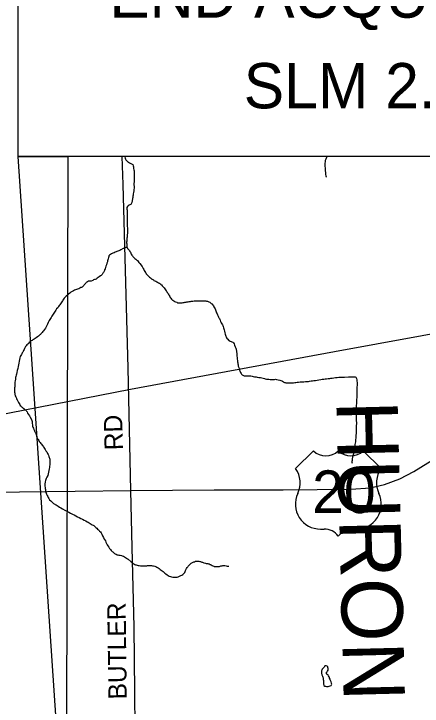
# Model space of a CAD drawing. Extents: x 0 to 34, y 0 to 22.
# Drawn here: x 6.547 to 7.808, y 17.578 to 19.717 of the extents above; entities that cross this region are included whole.
import ezdxf

# ---------------------------------------------------------------- set-up
doc = ezdxf.new("R2010")
doc.units = 0
for name, color, linetype in [('Default', 7, 'Continuous'), ('GM_X_Corporation', 7, 'Continuous'), ('GM_X_County_Road', 7, 'Continuous'), ('GM_X_County_Road_Text', 7, 'Continuous'), ('GM_X_County_Text', 7, 'Continuous'), ('GM_X_Minor_Lake', 7, 'Continuous'), ('GM_X_Minor_River', 7, 'Continuous'), ('GM_X_Rail_Line', 7, 'Continuous'), ('GM_X_US_Location', 7, 'Continuous'), ('GM_X_US_Route', 7, 'Continuous'), ('GM_X_US_Shield', 7, 'Continuous'), ('SH_Text', 7, 'Continuous')]:
    doc.layers.add(name, color=color, linetype=linetype)

msp = doc.modelspace()

# ---------------------------------------------------------------- linework, layer by layer
at = {"layer": 'Default'}
msp.add_lwpolyline([(6.7134, 19.2769), (6.7077, 17.0769), (6.5603, 19.2769)], close=True, dxfattribs=at)
at = {"layer": 'GM_X_Corporation'}
msp.add_lwpolyline([(8.0153, 15.2273), (7.992, 16.4534), (7.9799, 16.8298), (7.9733, 17.0489), (7.973, 17.0583), (7.9659, 17.2939), (7.9575, 17.6697), (7.951, 17.9078), (7.9387, 18.4008), (7.9196, 19.2769), (6.5603, 19.2769), (6.5603, 19.994)], dxfattribs=at)
msp.add_lwpolyline([(8.0153, 15.2273), (7.992, 16.4534), (7.9799, 16.8298), (7.9733, 17.0489), (7.973, 17.0583), (7.9659, 17.2939), (7.9575, 17.6697), (7.951, 17.9078), (7.9387, 18.4008), (7.9196, 19.2769), (6.5603, 19.2769), (6.5603, 19.994)], dxfattribs=at)
at = {"layer": 'GM_X_County_Road'}
for points in [[(6.9082, 18.2451), (6.8994, 18.6225), (6.8843, 19.1906), (6.8812, 19.2769)], [(6.9289, 17.0721), (6.923, 17.2763), (6.9202, 17.6229), (6.9177, 17.8238), (6.9125, 18.0684), (6.9082, 18.2451)]]:
    msp.add_lwpolyline(points, dxfattribs=at)
at = {"layer": 'GM_X_Minor_Lake'}
for points in [[(7.5068, 17.7034), (7.5068, 17.7034), (7.5054, 17.6994), (7.5038, 17.6974), (7.5018, 17.6958), (7.4991, 17.6928), (7.4976, 17.6897), (7.4968, 17.6871), (7.4964, 17.684), (7.4964, 17.6814), (7.4967, 17.6801)], [(7.5068, 17.7034), (7.5068, 17.7034), (7.5054, 17.6994), (7.5038, 17.6974), (7.5018, 17.6958), (7.4991, 17.6928), (7.4976, 17.6897), (7.4968, 17.6871), (7.4964, 17.684), (7.4964, 17.6814), (7.4967, 17.6801)], [(7.4967, 17.6801), (7.4979, 17.6753), (7.4987, 17.6734), (7.4994, 17.6711), (7.5009, 17.668), (7.5017, 17.6658), (7.502, 17.6627), (7.502, 17.6604), (7.5024, 17.6581), (7.5024, 17.6555), (7.5024, 17.6528), (7.5027, 17.6498), (7.5027, 17.6467), (7.5035, 17.6444), (7.5035, 17.6425), (7.5065, 17.6406), (7.5088, 17.6398), (7.5122, 17.6391), (7.5149, 17.639), (7.5175, 17.6394), (7.5206, 17.6401), (7.5233, 17.6409), (7.5267, 17.642), (7.5282, 17.6462), (7.5279, 17.6481), (7.5279, 17.65), (7.5268, 17.6538), (7.526, 17.6557), (7.5249, 17.658), (7.5237, 17.6599), (7.523, 17.6618), (7.5219, 17.6645), (7.5211, 17.6668), (7.52, 17.6694), (7.5188, 17.6717), (7.5173, 17.674), (7.5147, 17.6767), (7.5124, 17.6786), (7.5117, 17.6809), (7.5124, 17.6832), (7.5143, 17.6847), (7.5155, 17.687), (7.517, 17.6896), (7.5174, 17.6953), (7.5167, 17.698), (7.5159, 17.7003), (7.5137, 17.7022), (7.5114, 17.703), (7.5083, 17.7034), (7.5068, 17.7034)], [(7.4967, 17.6801), (7.4979, 17.6753), (7.4987, 17.6734), (7.4994, 17.6711), (7.5009, 17.668), (7.5017, 17.6658), (7.502, 17.6627), (7.502, 17.6604), (7.5024, 17.6581), (7.5024, 17.6555), (7.5024, 17.6528), (7.5027, 17.6498), (7.5027, 17.6467), (7.5035, 17.6444), (7.5035, 17.6425), (7.5065, 17.6406), (7.5088, 17.6398), (7.5122, 17.6391), (7.5149, 17.639), (7.5175, 17.6394), (7.5206, 17.6401), (7.5233, 17.6409), (7.5267, 17.642), (7.5282, 17.6462), (7.5279, 17.6481), (7.5279, 17.65), (7.5268, 17.6538), (7.526, 17.6557), (7.5249, 17.658), (7.5237, 17.6599), (7.523, 17.6618), (7.5219, 17.6645), (7.5211, 17.6668), (7.52, 17.6694), (7.5188, 17.6717), (7.5173, 17.674), (7.5147, 17.6767), (7.5124, 17.6786), (7.5117, 17.6809), (7.5124, 17.6832), (7.5143, 17.6847), (7.5155, 17.687), (7.517, 17.6896), (7.5174, 17.6953), (7.5167, 17.698), (7.5159, 17.7003), (7.5137, 17.7022), (7.5114, 17.703), (7.5083, 17.7034), (7.5068, 17.7034)]]:
    msp.add_lwpolyline(points, dxfattribs=at)
at = {"layer": 'GM_X_Minor_River'}
for points in [[(6.8891, 19.2769), (6.8894, 19.2751), (6.8902, 19.2717), (6.8917, 19.2686), (6.8928, 19.2667), (6.8947, 19.264), (6.8966, 19.2621), (6.8989, 19.2598), (6.9008, 19.2591), (6.9038, 19.2572), (6.9057, 19.256), (6.9076, 19.2552), (6.9095, 19.2541), (6.9118, 19.2533), (6.9141, 19.2514), (6.9156, 19.2476), (6.9159, 19.2442), (6.9163, 19.2396), (6.9174, 19.2351), (6.9178, 19.2324)], [(7.5136, 19.2769), (7.5119, 19.2736), (7.51, 19.2687), (7.5085, 19.2645), (7.5077, 19.2599), (7.5073, 19.2565), (7.5073, 19.2508), (7.5072, 19.2459), (7.5076, 19.2417), (7.508, 19.236), (7.5083, 19.2318), (7.5087, 19.2292), (7.5087, 19.2265), (7.509, 19.2227), (7.5098, 19.2151), (7.5124, 19.2136)], [(6.9178, 19.2324), (6.9181, 19.2278), (6.9185, 19.2221), (6.9185, 19.2168), (6.9184, 19.2126), (6.9184, 19.2096), (6.9184, 19.2062), (6.918, 19.2027), (6.918, 19.1993), (6.918, 19.1967), (6.9176, 19.194), (6.9179, 19.1788), (6.9175, 19.1746), (6.9171, 19.1704), (6.9163, 19.1659), (6.9155, 19.1617), (6.9147, 19.1575), (6.914, 19.1545), (6.9136, 19.1499), (6.9132, 19.1473), (6.9124, 19.1401), (6.9108, 19.1344), (6.9097, 19.1325), (6.9074, 19.1287), (6.9051, 19.1272), (6.9032, 19.126), (6.9001, 19.1238), (6.8978, 19.1219), (6.8959, 19.1192), (6.8959, 19.1139), (6.8963, 19.1109), (6.8962, 19.109), (6.8962, 19.1052), (6.8962, 19.1006), (6.8962, 19.0953), (6.8961, 19.0888), (6.8965, 19.0816), (6.8965, 19.0774), (6.8965, 19.0736), (6.8964, 19.071), (6.8964, 19.0656), (6.8971, 19.0516), (6.8975, 19.0478), (6.8975, 19.0447), (6.8971, 19.0425), (6.8971, 19.0394), (6.8966, 19.0345), (6.8966, 19.0307), (6.8962, 19.0273), (6.8958, 19.0246), (6.8958, 19.0223), (6.8954, 19.0189), (6.8954, 19.0147), (6.895, 19.0124), (6.895, 19.0102), (6.8954, 19.0067), (6.8954, 19.0041), (6.8953, 19.0007), (6.8953, 18.998), (6.8961, 18.9957), (6.898, 18.9919), (6.9006, 18.9888), (6.9033, 18.9858), (6.9052, 18.9831), (6.9067, 18.9808), (6.9093, 18.9744), (6.9112, 18.9713), (6.9131, 18.9694), (6.9142, 18.9675), (6.9172, 18.9648), (6.9188, 18.9629), (6.9207, 18.9614), (6.9233, 18.9595), (6.9263, 18.9568), (6.9286, 18.9549), (6.9309, 18.9526), (6.9331, 18.9495), (6.9354, 18.9461), (6.9426, 18.9366), (6.9445, 18.9331), (6.946, 18.9305), (6.9479, 18.9274), (6.9494, 18.9244), (6.9513, 18.9213), (6.9528, 18.9187), (6.9539, 18.9168), (6.9554, 18.9145), (6.9569, 18.9122), (6.9592, 18.9099), (6.9619, 18.9076), (6.9653, 18.9042), (6.9687, 18.9015), (6.9713, 18.8996), (6.9732, 18.898), (6.9755, 18.8965), (6.9774, 18.8954), (6.9793, 18.8938), (6.9816, 18.8923), (6.9846, 18.8911), (6.9877, 18.8896), (6.9907, 18.8881)], [(6.896, 18.9959), (6.8946, 18.9957), (6.8927, 18.9953), (6.89, 18.9942), (6.8866, 18.9927), (6.8846, 18.992), (6.8766, 18.9878), (6.8736, 18.9863), (6.8675, 18.9837), (6.8648, 18.9829), (6.8621, 18.9818), (6.8591, 18.9807), (6.8564, 18.9792), (6.8526, 18.9784), (6.8499, 18.9773), (6.8477, 18.9758), (6.8446, 18.9743), (6.8419, 18.9713), (6.84, 18.9698), (6.8396, 18.9679), (6.8389, 18.9644), (6.8377, 18.9603), (6.8369, 18.9569), (6.8361, 18.9542), (6.8354, 18.9512), (6.8342, 18.947), (6.8327, 18.9424), (6.8311, 18.9379), (6.8296, 18.9333), (6.8284, 18.9295), (6.8269, 18.9269), (6.8265, 18.9246), (6.8257, 18.9227), (6.8246, 18.9204), (6.823, 18.9182), (6.8215, 18.9159), (6.8192, 18.9121), (6.8165, 18.9091), (6.8142, 18.9076), (6.8104, 18.9049), (6.8074, 18.9026), (6.8039, 18.9004), (6.8009, 18.8981), (6.7978, 18.897), (6.7959, 18.8966), (6.7929, 18.8951), (6.7906, 18.8936), (6.7856, 18.891), (6.7818, 18.891), (6.7795, 18.8914), (6.7776, 18.891), (6.7738, 18.8899), (6.7704, 18.8869), (6.7688, 18.885), (6.7662, 18.8819), (6.7642, 18.8797), (6.7627, 18.8778), (6.7597, 18.8747), (6.7577, 18.8732), (6.7558, 18.8721), (6.7536, 18.8714), (6.7505, 18.8702), (6.7471, 18.8683), (6.7429, 18.8672), (6.7402, 18.8657), (6.7372, 18.865), (6.7341, 18.8635), (6.7307, 18.8616), (6.7269, 18.8597), (6.723, 18.8574), (6.7196, 18.8548), (6.7158, 18.8518), (6.712, 18.8484), (6.7085, 18.8453), (6.7047, 18.8416), (6.7024, 18.8389), (6.7001, 18.8363), (6.6982, 18.8332), (6.6967, 18.8306), (6.6947, 18.8276), (6.6924, 18.8241), (6.6905, 18.8215), (6.6886, 18.8188), (6.6867, 18.8162), (6.6848, 18.8132), (6.6821, 18.809), (6.6787, 18.8056), (6.6764, 18.8018), (6.6679, 18.7897), (6.666, 18.7866), (6.6637, 18.7829), (6.6614, 18.7794), (6.6595, 18.776), (6.658, 18.773), (6.656, 18.7696), (6.653, 18.7635), (6.6507, 18.759), (6.6484, 18.7548), (6.6464, 18.7503), (6.6441, 18.7461), (6.6411, 18.7419)], [(6.9907, 18.8881), (6.9937, 18.8865), (6.9964, 18.885), (6.999, 18.8831), (7.0009, 18.8816), (7.0024, 18.8797), (7.0047, 18.8774), (7.0066, 18.8755), (7.0081, 18.8736), (7.0104, 18.8709), (7.0127, 18.8678), (7.0149, 18.8644), (7.0172, 18.8617), (7.0187, 18.8594), (7.0202, 18.8568), (7.0217, 18.8545), (7.0232, 18.8526), (7.0251, 18.8495), (7.0266, 18.8469), (7.0282, 18.8438), (7.0297, 18.8411), (7.0312, 18.8389), (7.0331, 18.8362), (7.0353, 18.8339), (7.0376, 18.8324), (7.0403, 18.8304), (7.0429, 18.8289), (7.0456, 18.8278), (7.0501, 18.8262), (7.0524, 18.8247), (7.0547, 18.8243), (7.0574, 18.8243), (7.0604, 18.8243), (7.0634, 18.8246), (7.0665, 18.825), (7.0692, 18.8254), (7.0722, 18.8257), (7.0745, 18.8261), (7.0768, 18.8265), (7.0787, 18.8268), (7.081, 18.8272), (7.0848, 18.828), (7.0878, 18.8283), (7.0905, 18.8291), (7.0924, 18.8291), (7.0947, 18.8294), (7.097, 18.8298), (7.0996, 18.8298), (7.103, 18.8305), (7.1061, 18.8305), (7.1095, 18.8309), (7.1137, 18.8309), (7.1194, 18.8308), (7.1236, 18.8304), (7.1274, 18.8304), (7.1304, 18.8304), (7.1331, 18.8304), (7.1354, 18.8304), (7.1377, 18.8304), (7.1396, 18.8303), (7.1415, 18.83), (7.1449, 18.8296), (7.1491, 18.8276), (7.1517, 18.8261), (7.154, 18.8242), (7.1563, 18.8227), (7.1582, 18.8211), (7.1631, 18.815), (7.1646, 18.8124), (7.1661, 18.8093), (7.168, 18.8055), (7.1703, 18.8002), (7.1718, 18.7967), (7.1729, 18.7941), (7.1744, 18.7907), (7.1759, 18.7872), (7.1774, 18.7834), (7.1789, 18.7804), (7.18, 18.7785), (7.1815, 18.7758), (7.1827, 18.7731), (7.1834, 18.7705), (7.1846, 18.7667), (7.1857, 18.7644), (7.1868, 18.7625), (7.1891, 18.7594), (7.191, 18.7567), (7.1917, 18.7545), (7.1928, 18.7514), (7.1944, 18.7476), (7.1958, 18.7415), (7.1973, 18.7366), (7.1985, 18.732), (7.1996, 18.7278), (7.2003, 18.7248), (7.2015, 18.7214), (7.2022, 18.7191), (7.2037, 18.716), (7.2056, 18.7133), (7.2075, 18.7118), (7.209, 18.7095)], [(6.6411, 18.7419), (6.6384, 18.7385), (6.6361, 18.7359), (6.6338, 18.7332), (6.6319, 18.7309), (6.63, 18.729), (6.6288, 18.7272), (6.6265, 18.7256), (6.6231, 18.7219), (6.6193, 18.7192), (6.6158, 18.7166), (6.6124, 18.7139), (6.6097, 18.712), (6.6074, 18.7109), (6.6055, 18.7098), (6.6032, 18.7083), (6.6006, 18.7068), (6.5967, 18.7037), (6.5941, 18.7015), (6.5914, 18.6992), (6.5895, 18.6969), (6.5872, 18.6947), (6.5849, 18.692), (6.583, 18.6897), (6.5807, 18.6856), (6.5791, 18.6833), (6.578, 18.6803), (6.5768, 18.6769), (6.5757, 18.6746), (6.5741, 18.6723), (6.5726, 18.6697), (6.5711, 18.6674), (6.5699, 18.6651), (6.5684, 18.6621), (6.5665, 18.6587), (6.5653, 18.6545), (6.563, 18.6442), (6.5618, 18.6378), (6.561, 18.6325), (6.5598, 18.6275), (6.5587, 18.6215), (6.5571, 18.615), (6.5556, 18.6089), (6.5544, 18.6044), (6.5536, 18.601), (6.5525, 18.5972), (6.5517, 18.5934), (6.5513, 18.5892), (6.5509, 18.5839), (6.5501, 18.5793), (6.5497, 18.5755), (6.5493, 18.5721), (6.5493, 18.5687), (6.5493, 18.5652), (6.5489, 18.5615), (6.5489, 18.5576), (6.5485, 18.5546), (6.5484, 18.5527), (6.5484, 18.5504), (6.5488, 18.5485), (6.5496, 18.5459), (6.5499, 18.5424), (6.551, 18.5375), (6.5525, 18.5337), (6.5537, 18.5318), (6.5544, 18.5284), (6.5567, 18.5245), (6.5589, 18.5207), (6.5612, 18.5169), (6.5627, 18.5139), (6.5646, 18.5108), (6.5661, 18.5074), (6.5688, 18.5051), (6.5703, 18.5032), (6.5726, 18.5017), (6.5744, 18.4998), (6.5771, 18.4978), (6.5798, 18.4959), (6.5824, 18.4936), (6.5843, 18.4921), (6.5858, 18.4902), (6.5873, 18.4879), (6.5892, 18.4841), (6.5922, 18.4791), (6.5949, 18.4753), (6.5971, 18.4715), (6.6017, 18.4624), (6.602, 18.4605), (6.6028, 18.4578), (6.6032, 18.4548), (6.6035, 18.4513), (6.6039, 18.4479), (6.6046, 18.4434), (6.6057, 18.4407), (6.6069, 18.4373), (6.6084, 18.4335), (6.6099, 18.4289), (6.6118, 18.4258), (6.6133, 18.4236), (6.6148, 18.4205), (6.6155, 18.4175)], [(7.209, 18.7095), (7.212, 18.708), (7.2151, 18.7065), (7.2174, 18.7053), (7.22, 18.7042), (7.2227, 18.7026), (7.2246, 18.7007), (7.2265, 18.6977), (7.2283, 18.6935), (7.2302, 18.6889), (7.2321, 18.6847), (7.2332, 18.6817), (7.2351, 18.6668), (7.2354, 18.6604), (7.2361, 18.6547), (7.2365, 18.6509), (7.2372, 18.6467), (7.2376, 18.6421), (7.238, 18.6387), (7.2383, 18.636), (7.2391, 18.633), (7.2398, 18.6284), (7.2409, 18.625), (7.2421, 18.6204), (7.2432, 18.617), (7.2443, 18.614), (7.2454, 18.6109), (7.2466, 18.609), (7.2485, 18.606), (7.25, 18.6041), (7.2519, 18.6021), (7.2541, 18.6006), (7.2579, 18.5995), (7.261, 18.5994), (7.2644, 18.5994), (7.2678, 18.5994), (7.2713, 18.5994), (7.2751, 18.599), (7.2785, 18.5986), (7.2823, 18.5978), (7.2861, 18.597), (7.2903, 18.5963), (7.2945, 18.5955), (7.2983, 18.5947), (7.3036, 18.5943), (7.3081, 18.5935), (7.3127, 18.5924), (7.3169, 18.5916), (7.3203, 18.5908), (7.323, 18.59), (7.3264, 18.5892), (7.3298, 18.5888), (7.334, 18.5884), (7.3378, 18.5881), (7.3416, 18.5877), (7.3443, 18.5876), (7.3462, 18.5876), (7.3485, 18.588), (7.3511, 18.588), (7.3545, 18.5884), (7.358, 18.588), (7.3682, 18.586), (7.3713, 18.5848), (7.3739, 18.5837), (7.3762, 18.5822), (7.3789, 18.5806), (7.3808, 18.5795), (7.3827, 18.5787), (7.3846, 18.5779), (7.3865, 18.5776), (7.3887, 18.5772), (7.391, 18.5772), (7.3937, 18.5771), (7.3971, 18.5771), (7.4005, 18.5771), (7.4047, 18.5775), (7.41, 18.5778), (7.4139, 18.5782), (7.4177, 18.5785), (7.4211, 18.5793), (7.4253, 18.5796), (7.4306, 18.58), (7.4367, 18.5804), (7.4424, 18.5807), (7.4477, 18.5811), (7.4523, 18.5814), (7.4561, 18.5818), (7.4595, 18.5825), (7.4645, 18.5833), (7.4687, 18.584), (7.4732, 18.5847), (7.4782, 18.5851), (7.4835, 18.5858), (7.4889, 18.5869), (7.4942, 18.5877), (7.4991, 18.5888), (7.5037, 18.5891), (7.5083, 18.5895), (7.5125, 18.5899), (7.5178, 18.5906), (7.522, 18.591)], [(7.522, 18.591), (7.5258, 18.5913), (7.53, 18.5917), (7.5345, 18.5928), (7.5395, 18.5935), (7.5448, 18.5943), (7.5498, 18.5946), (7.5543, 18.595), (7.5589, 18.5953), (7.5635, 18.5953), (7.568, 18.5953), (7.5798, 18.5956), (7.5817, 18.5956), (7.584, 18.5956), (7.5859, 18.596), (7.5882, 18.596), (7.5909, 18.596), (7.5935, 18.5959), (7.5958, 18.5959), (7.5981, 18.5959), (7.6004, 18.5955), (7.603, 18.5944), (7.6046, 18.5909), (7.6057, 18.5864), (7.606, 18.583), (7.6064, 18.5788), (7.6068, 18.5742), (7.6064, 18.57), (7.6063, 18.5643), (7.6059, 18.5579), (7.6059, 18.5514), (7.6059, 18.545), (7.6054, 18.5385), (7.6054, 18.532), (7.605, 18.526), (7.605, 18.5199), (7.6046, 18.5134), (7.6038, 18.5073), (7.6037, 18.5024), (7.6033, 18.4997), (7.6037, 18.4956), (7.6041, 18.4906), (7.604, 18.4857), (7.604, 18.4811), (7.604, 18.4769), (7.604, 18.4727), (7.6036, 18.4682), (7.6039, 18.4636), (7.6039, 18.4598), (7.6043, 18.4545), (7.6043, 18.4507), (7.6042, 18.4458), (7.6042, 18.442), (7.6042, 18.4374), (7.6042, 18.4321), (7.6038, 18.426), (7.6025, 18.4108), (7.6025, 18.4066), (7.6021, 18.4021), (7.6017, 18.3956), (7.6009, 18.3907), (7.6001, 18.3869), (7.5997, 18.3831), (7.599, 18.3789), (7.5982, 18.3743), (7.5974, 18.3694), (7.5962, 18.3641), (7.5951, 18.3584), (7.5939, 18.3523), (7.5927, 18.3489), (7.5923, 18.3455), (7.5919, 18.3432), (7.5919, 18.3405), (7.5912, 18.3371), (7.5908, 18.3345), (7.5904, 18.3318), (7.5915, 18.3295), (7.5915, 18.3288), (7.5915, 18.3295)], [(6.6155, 18.4175), (6.6163, 18.4148), (6.617, 18.4118), (6.6189, 18.4072), (6.6204, 18.4038), (6.6219, 18.4018), (6.6234, 18.3992), (6.6253, 18.3965), (6.6276, 18.3935), (6.6299, 18.3904), (6.6325, 18.3877), (6.6344, 18.3851), (6.6363, 18.3824), (6.6382, 18.3801), (6.6397, 18.3778), (6.6416, 18.3748), (6.6438, 18.3713), (6.6457, 18.3675), (6.648, 18.3637), (6.6503, 18.3595), (6.6521, 18.3561), (6.6533, 18.3534), (6.6548, 18.3496), (6.6555, 18.347), (6.6567, 18.3447), (6.6574, 18.3412), (6.6578, 18.3378), (6.6581, 18.3336), (6.6577, 18.3295), (6.6573, 18.3245), (6.6569, 18.3196), (6.6565, 18.3154), (6.6557, 18.3112), (6.6549, 18.3063), (6.6511, 18.2907), (6.6484, 18.2862), (6.6465, 18.282), (6.6453, 18.279), (6.6441, 18.2756), (6.6434, 18.2718), (6.643, 18.2687), (6.6426, 18.2664), (6.6426, 18.263), (6.6425, 18.2581), (6.6429, 18.2539), (6.6433, 18.2509), (6.644, 18.2478), (6.6444, 18.2444), (6.6451, 18.2417), (6.6459, 18.2394), (6.6466, 18.2368), (6.6478, 18.2337), (6.6485, 18.2311), (6.6496, 18.2288), (6.6511, 18.2261), (6.6526, 18.2231), (6.6545, 18.22), (6.6572, 18.2158), (6.661, 18.2124), (6.6648, 18.2082), (6.6693, 18.2047), (6.6727, 18.2028), (6.6746, 18.2017), (6.6773, 18.2001), (6.6803, 18.1982), (6.6837, 18.1959), (6.6879, 18.1936), (6.6921, 18.191), (6.6966, 18.1883), (6.7042, 18.1844), (6.7103, 18.181), (6.7167, 18.1779), (6.722, 18.1752), (6.7274, 18.1718), (6.7327, 18.1691), (6.738, 18.1664), (6.7429, 18.1637), (6.7482, 18.161), (6.7536, 18.1587), (6.7589, 18.156), (6.7638, 18.153), (6.7691, 18.1507), (6.7729, 18.1484), (6.7763, 18.1465), (6.7854, 18.1407), (6.7885, 18.1388), (6.7919, 18.1373), (6.7938, 18.1365), (6.7957, 18.1346), (6.7979, 18.1327), (6.8002, 18.1308), (6.8025, 18.1285), (6.8051, 18.1258), (6.8078, 18.1235), (6.8097, 18.1216), (6.8116, 18.1193), (6.8139, 18.1166), (6.8161, 18.1136), (6.8184, 18.1098), (6.8206, 18.1052), (6.8233, 18.0991)], [(6.8233, 18.0991), (6.8259, 18.0949), (6.8278, 18.0919), (6.8293, 18.0888), (6.8308, 18.085), (6.8327, 18.0812), (6.835, 18.0774), (6.8372, 18.0736), (6.8399, 18.0694), (6.8425, 18.0659), (6.8452, 18.0629), (6.8474, 18.0598), (6.8501, 18.0568), (6.852, 18.0549), (6.8554, 18.0518), (6.8573, 18.0503), (6.8599, 18.0488), (6.8622, 18.0476), (6.8653, 18.0465), (6.8679, 18.0457), (6.871, 18.0453), (6.8732, 18.0449), (6.8751, 18.0445), (6.8786, 18.0437), (6.8816, 18.043), (6.885, 18.0414), (6.8884, 18.0395), (6.8915, 18.0376), (6.8945, 18.0357), (6.8972, 18.0341), (6.8994, 18.0322), (6.9089, 18.0242), (6.9116, 18.0223), (6.9142, 18.0204), (6.9173, 18.0185), (6.9203, 18.0165), (6.9226, 18.0154), (6.9248, 18.0146), (6.9271, 18.0139), (6.9302, 18.0131), (6.9336, 18.0127), (6.9378, 18.0123), (6.942, 18.0119), (6.9465, 18.0119), (6.9496, 18.0115), (6.9515, 18.0115), (6.9553, 18.0118), (6.9572, 18.0122), (6.9595, 18.0126), (6.9618, 18.0129), (6.9644, 18.0133), (6.9686, 18.0133), (6.9716, 18.0129), (6.9747, 18.0125), (6.9781, 18.0117), (6.9815, 18.0109), (6.9849, 18.0098), (6.9887, 18.0079), (6.9922, 18.0056), (6.9956, 18.0033), (6.9986, 18.001), (7.0016, 17.9987), (7.0043, 17.9964), (7.0081, 17.9941), (7.0104, 17.9918), (7.013, 17.9895), (7.0164, 17.9868), (7.0198, 17.9845), (7.0232, 17.9822), (7.0267, 17.9803), (7.0301, 17.9791), (7.0339, 17.978), (7.0377, 17.9772), (7.0411, 17.9768), (7.0449, 17.9768), (7.0476, 17.9772), (7.0506, 17.9775), (7.0537, 17.9783), (7.0628, 17.9817), (7.0651, 17.9828), (7.0685, 17.9854), (7.0705, 17.9869), (7.0724, 17.9896), (7.0743, 17.9919), (7.0754, 17.9949), (7.0766, 17.9972), (7.0774, 17.9994), (7.0785, 18.0017), (7.0797, 18.004), (7.082, 18.0066), (7.0835, 18.0089), (7.0854, 18.0112), (7.0866, 18.0131), (7.0896, 18.0161), (7.0915, 18.0176), (7.0946, 18.0199), (7.098, 18.0218), (7.1003, 18.0229), (7.1022, 18.024), (7.1041, 18.0248), (7.1072, 18.0263)], [(7.1072, 18.0263), (7.1095, 18.0263), (7.1117, 18.0266), (7.114, 18.0266), (7.1159, 18.0266), (7.1182, 18.0262), (7.1205, 18.0258), (7.1228, 18.0251), (7.125, 18.0243), (7.1269, 18.0235), (7.1288, 18.0231), (7.1311, 18.0224), (7.133, 18.0216), (7.1383, 18.0201), (7.1406, 18.0197), (7.1429, 18.0193), (7.1452, 18.0189), (7.1478, 18.0181), (7.1501, 18.0177), (7.152, 18.0166), (7.1543, 18.0158), (7.1562, 18.0146), (7.1592, 18.0127), (7.1611, 18.0116), (7.1638, 18.0108), (7.1657, 18.0104), (7.1687, 18.01), (7.1718, 18.0096), (7.1752, 18.0096), (7.1779, 18.01), (7.1798, 18.01), (7.1821, 18.0103), (7.1855, 18.0115), (7.1874, 18.0118), (7.1901, 18.0122), (7.1923, 18.0126), (7.1942, 18.0126), (7.1961, 18.0126), (7.1984, 18.0129), (7.2018, 18.0121), (7.2049, 18.0114), (7.2068, 18.011), (7.2091, 18.0106), (7.2102, 18.0106)]]:
    msp.add_lwpolyline(points, dxfattribs=at)
at = {"layer": 'GM_X_Rail_Line'}
msp.add_lwpolyline([(2.1, 18.3652), (2.4476, 18.3515), (3.7542, 18.2908), (4.7355, 18.2536), (4.912, 18.2502), (5.0326, 18.2535), (5.2097, 18.2563), (5.4881, 18.3005), (6.2957, 18.4383), (6.9068, 18.5576), (7.5368, 18.6745), (7.9374, 18.7476)], dxfattribs=at)
at = {"layer": 'GM_X_US_Route'}
msp.add_lwpolyline([(5.4163, 18.2283), (5.4371, 18.2285), (5.6077, 18.2299), (6.0537, 18.236), (6.391, 18.2389), (6.9082, 18.2451), (7.1657, 18.2463), (7.3782, 18.2472), (7.5886, 18.2484), (7.6469, 18.2534), (7.6916, 18.2633), (7.7387, 18.2806), (7.7821, 18.3038), (7.8813, 18.3654), (7.9389, 18.4003)], dxfattribs=at)
at = {"layer": 'GM_X_US_Shield'}
for p, q in [((7.4718, 18.3673), (7.4169, 18.3123)), ((7.6805, 18.3123), (7.6256, 18.3673)), ((7.4938, 18.1256), (7.5047, 18.1256)), ((7.5926, 18.1256), (7.6036, 18.1256))]:
    msp.add_line(p, q, dxfattribs=at)
for centre, radius, start, end in [((7.5102, 18.4065), 0.0549, 225.573, 314.427), ((7.5871, 18.4065), 0.0549, 225.573, 314.427), ((7.3539, 18.2682), 0.0769, 334.5471, 35.0009), ((7.7435, 18.2682), 0.0769, 144.9991, 205.4529), ((7.4929, 18.2025), 0.0769, 154.8319, 270.6383), ((7.6045, 18.2025), 0.0769, 269.3617, 25.1681), ((7.5047, 18.0706), 0.0549, 36.8699, 90), ((7.5926, 18.0706), 0.0549, 90, 143.1301)]:
    msp.add_arc(centre, radius, start, end, dxfattribs=at)
at = {"layer": 'SH_Text'}
msp.add_lwpolyline([(6.5603, 19.994), (8.7801, 19.994), (8.7801, 19.2769), (6.5603, 19.2769)], close=True, dxfattribs=at)

# ---------------------------------------------------------------- texts
at = {"layer": 'GM_X_County_Road_Text'}
for s, rotation, p in [('RD', 91.4844, (6.8838, 18.3698)), ('BUTLER', 90.7091, (6.8955, 17.5995))]:
    msp.add_text(s, height=0.05682, rotation=rotation, dxfattribs=at).set_placement(p)
at = {"layer": 'GM_X_County_Text'}
msp.add_text('HURON COUNTY', height=0.189394, rotation=271.4235, dxfattribs=at).set_placement((7.5424, 18.5207))
at = {"layer": 'GM_X_US_Location'}
for s in ['0', '/']:
    msp.add_text(s, height=0.000189, dxfattribs=at).set_placement((7.5486, 18.2399))
msp.add_text('20', height=0.000189, rotation=0, dxfattribs=at).set_placement((7.5095, 18.2007))
at = {"layer": 'GM_X_US_Shield'}
msp.add_text('20', height=0.13184, dxfattribs=at).set_placement((7.4678, 18.175))
at = {"layer": 'SH_Text'}
for s, p in [('END ACQUISTION', (6.8413, 19.7054)), ('SLM 2.44', (7.2565, 19.4254))]:
    msp.add_text(s, height=0.14, dxfattribs=at).set_placement(p)

doc.saveas('drawing.dxf')
